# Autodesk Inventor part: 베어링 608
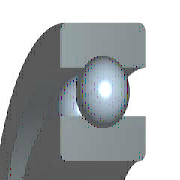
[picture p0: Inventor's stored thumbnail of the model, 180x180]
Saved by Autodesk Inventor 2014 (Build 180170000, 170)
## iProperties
IsCustomPart: 1
Created: 2012-02
Part Number: 베어링 608
Material: 강철, 연강
Description: 깊은 그루브 볼 베어링
Document SubType Name: Modeling
Standard: KS B 2023
Designer: mduedu
Standards Organization: KS
Language: ko-KR
Size Designation: 608 - 8 x 22 x 7
Categories: <MemberInstance><Categories><Category DisplayName="샤프트 부품" InternalName="7f7aeb1f-a693-4053-b835-cee3144e0d98" Mnemonic="SHFT"><Category DisplayName="베어링" Inter
Density: 7.86 g/cm^3
Appearance: Orange
Mass: 10.9696 g
Surface Area: 20.0754 cm^2
Volume: 1.39562 cm^3
Author: mduedu
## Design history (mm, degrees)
sketch "스케치" dims "d0" = 3.64 (= -0.26 x WD + 0.26 x BD)
  geometry: L1 (1.68, 7.5)-(5.32, 7.5); L2 (3.5, 7.5)-(3.5, 5.68); L3 (3.5, 7.5)-(3.5, 9.32); L4 (2.148, 6.282)-(0, 6.282); L5 (0, 4)-(7, 4); L6 (2.148, 8.718)-(0, 8.718); L7 (0, 11)-(7, 11); L8 (7, 4)-(7, 6.282); L9 (4.852, 6.282)-(7, 6.282); L10 (4.852, 8.718)-(7, 8.718); L11 (7, 11)-(7, 8.718); L12 (-1.4, 0)-(8.4, 0) reference; L13 (0, -0.3)-(0, 5.3) reference
  constraints: 22 end point, 4 point on line, 2 collinear, 2 perpendicular, 2 symmetric about line, 1 midpoint, 1 parallel, 14 other
  dimensions: "d9" = 8 diameter of L5 L12 (= WD); "d11" = 22 diameter of L7 L12 (= BD); "d12" = 7 distance between parallel lines of L8 L13 (= KB); "d13" = 12.564 diameter of L9 L12 (= 0.326 x BD + 0.674 x WD)
revolve "본체" stored, may be unused: angle "d6" = 90 deg
revolve "볼" stored, may be unused: angle "d7" = 90 deg
pattern_circular "IDS_ARRAYBALL[SIMPL:T]" dims angle "d3" = 360 deg
body "Solid1"
fillet "모깎기1" dims "d1" = 0.3 (= KRS)
other parameters: "WD" = 8 [user parameter; used in 5 equation terms], "BD" = 22 [user parameter; used in 5 equation terms], "KB" = 7 [user parameter; used in 1 equation term], "KRS" = 0.3 [user parameter; used in 1 equation term], "d4" = 0, "d5" = 0, "d8" = 0, "d14" = 0, "d15" = 0, "BBA" = 0 [user parameter], "BC0" = 1370000 [user parameter], "BC" = 3250000 [user parameter], "BR" = 11 (= 0.5 x BD) [user parameter], "WR" = 4 (= 0.5 x WD) [user parameter]
